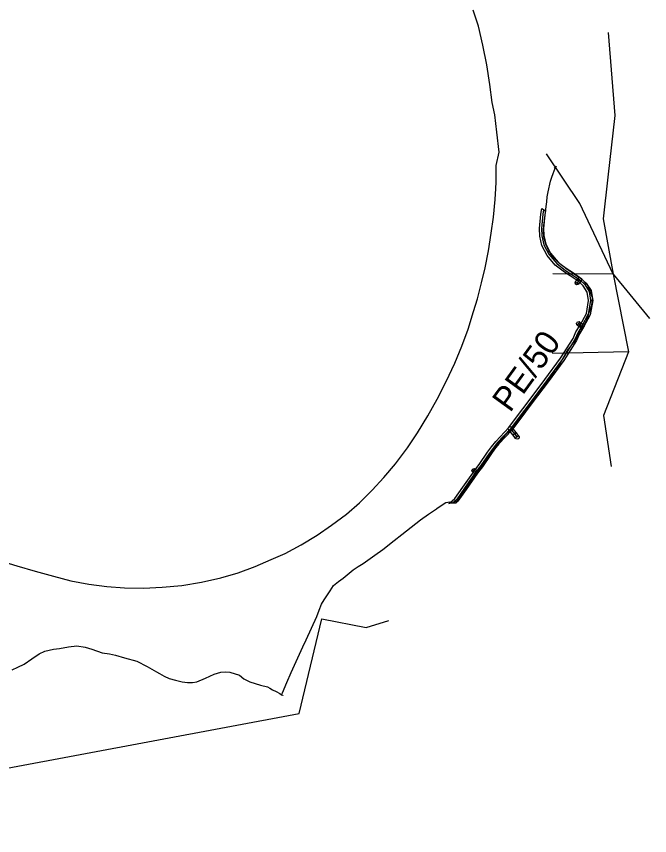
# Model space of a CAD drawing. Extents: x -555222 to -543220, y -1067119 to -1030889.
# Drawn here: x -549859.6 to -549545, y -1042854.2 to -1042447 of the extents above; entities that cross this region are included whole.
import ezdxf

# ---------------------------------------------------------------- set-up
doc = ezdxf.new("R2010")
doc.units = 0
for name, color, linetype in [('07_KANALIZACE', 7, 'Continuous'), ('07_OCH_P A POPISY TI', 7, 'Continuous'), ('07_PLYNOVOD', 7, 'Continuous'), ('07_SDĚLOVACÍ', 7, 'Continuous'), ('07_VODOVOD', 7, 'Continuous')]:
    doc.layers.add(name, color=color, linetype=linetype)

msp = doc.modelspace()

# ---------------------------------------------------------------- linework, layer by layer
at = {"layer": '07_KANALIZACE'}
msp.add_lwpolyline([(-550044.93, -1042883.73), (-550009.42, -1042847.76), (-549719.11, -1042793.56), (-549707.75, -1042746.36), (-549685.88, -1042750.73), (-549674.52, -1042747.24)], dxfattribs=at)
at = {"layer": '07_OCH_P A POPISY TI'}
for p, q in [((-549598.98, -1042545.22), (-549598.6, -1042542.52)), ((-549598.6, -1042542.52), (-549596.74, -1042543.68)), ((-549599.64, -1042552.35), (-549598.98, -1042545.22)), ((-549597, -1042545.46), (-549597.64, -1042552.39)), ((-549596.74, -1042543.68), (-549597, -1042545.46)), ((-549599.44, -1042556.17), (-549599.64, -1042552.35)), ((-549597.64, -1042552.39), (-549597.46, -1042555.91)), ((-549598.46, -1042560.84), (-549599.44, -1042556.17)), ((-549597.46, -1042555.91), (-549596.56, -1042560.16)), ((-549595.93, -1042565.77), (-549598.46, -1042560.84)), ((-549596.56, -1042560.16), (-549594.25, -1042564.65)), ((-549591.82, -1042570.6), (-549595.93, -1042565.77)), ((-549594.25, -1042564.65), (-549590.42, -1042569.14)), ((-549587.28, -1042574.12), (-549591.82, -1042570.6)), ((-549590.42, -1042569.14), (-549586.1, -1042572.5)), ((-549584.53, -1042576), (-549587.28, -1042574.12)), ((-549586.1, -1042572.5), (-549583.41, -1042574.34)), ((-549583.41, -1042574.34), (-549579.28, -1042577.05)), ((-549580.5, -1042578.65), (-549584.53, -1042576)), ((-549582.01, -1042579.22), (-549581.78, -1042578.87)), ((-549581.85, -1042580.03), (-549582.01, -1042579.22)), ((-549581.78, -1042578.87), (-549581.36, -1042578.24)), ((-549581.59, -1042578.58), (-549581.36, -1042578.24)), ((-549581.43, -1042579.4), (-549581.59, -1042578.58)), ((-549581.08, -1042579.63), (-549581.43, -1042579.4)), ((-549581.36, -1042578.24), (-549580.72, -1042577.29)), ((-549581.36, -1042578.24), (-549581.12, -1042577.9)), ((-549581.12, -1042577.9), (-549580.31, -1042577.74)), ((-549580.74, -1042579.86), (-549581.08, -1042579.63)), ((-549579.93, -1042579.7), (-549580.74, -1042579.86)), ((-549580.72, -1042577.29), (-549580.49, -1042576.95)), ((-549577.98, -1042580.89), (-549580.5, -1042578.65)), ((-549580.49, -1042576.95), (-549579.68, -1042576.79)), ((-549580.31, -1042577.74), (-549579.97, -1042577.97)), ((-549579.7, -1042579.36), (-549580.12, -1042579.99)), ((-549579.97, -1042577.97), (-549579.62, -1042578.2)), ((-549579.7, -1042579.36), (-549579.93, -1042579.7)), ((-549579.06, -1042578.41), (-549579.7, -1042579.36)), ((-549579.46, -1042579.01), (-549579.7, -1042579.36)), ((-549579.68, -1042576.79), (-549579.33, -1042577.02)), ((-549579.62, -1042578.2), (-549579.46, -1042579.01)), ((-549579.33, -1042577.02), (-549578.99, -1042577.25)), ((-549579.28, -1042577.05), (-549576.44, -1042579.57)), ((-549578.83, -1042578.06), (-549579.06, -1042578.41)), ((-549578.99, -1042577.25), (-549578.83, -1042578.06)), ((-549576.44, -1042579.57), (-549574.03, -1042583.31)), ((-549581.51, -1042580.26), (-549581.85, -1042580.03)), ((-549581.16, -1042580.49), (-549581.51, -1042580.26)), ((-549580.35, -1042580.33), (-549581.16, -1042580.49)), ((-549580.12, -1042579.99), (-549580.35, -1042580.33)), ((-549575.93, -1042584.05), (-549577.98, -1042580.89)), ((-549574.03, -1042583.31), (-549573.26, -1042588.15)), ((-549575.28, -1042588.13), (-549575.93, -1042584.05)), ((-549576.41, -1042594.73), (-549575.28, -1042588.13)), ((-549573.26, -1042588.15), (-549574.49, -1042595.39)), ((-549579.49, -1042600.44), (-549576.41, -1042594.73)), ((-549574.49, -1042595.39), (-549577.75, -1042601.44)), ((-549581.27, -1042599.53), (-549581.03, -1042599.19)), ((-549581.14, -1042600.35), (-549581.27, -1042599.53)), ((-549581.03, -1042599.19), (-549580.79, -1042598.86)), ((-549580.79, -1042598.86), (-549579.97, -1042598.73)), ((-549580.57, -1042600.04), (-549580.33, -1042599.7)), ((-549580.44, -1042600.86), (-549580.57, -1042600.04)), ((-549580.33, -1042599.7), (-549580.09, -1042599.37)), ((-549580.09, -1042599.37), (-549579.27, -1042599.24)), ((-549579.97, -1042598.73), (-549579.63, -1042598.97)), ((-549579.63, -1042598.97), (-549578.93, -1042599.48)), ((-549579.27, -1042599.24), (-549578.93, -1042599.48)), ((-549578.93, -1042599.48), (-549578.03, -1042600.13)), ((-549578.93, -1042599.48), (-549578.6, -1042599.72)), ((-549578.6, -1042599.72), (-549578.47, -1042600.54)), ((-549578.03, -1042600.13), (-549577.7, -1042600.37)), ((-549583.01, -1042607.1), (-549581.57, -1042603.8)), ((-549581.57, -1042603.8), (-549579.49, -1042600.44)), ((-549580.81, -1042600.59), (-549581.14, -1042600.35)), ((-549580.11, -1042601.1), (-549580.81, -1042600.59)), ((-549580.11, -1042601.1), (-549580.44, -1042600.86)), ((-549579.21, -1042601.75), (-549580.11, -1042601.1)), ((-549579.77, -1042601.34), (-549580.11, -1042601.1)), ((-549577.75, -1042601.44), (-549579.79, -1042604.74)), ((-549578.95, -1042601.21), (-549579.77, -1042601.34)), ((-549578.87, -1042601.99), (-549579.21, -1042601.75)), ((-549578.71, -1042600.88), (-549578.95, -1042601.21)), ((-549578.05, -1042601.86), (-549578.87, -1042601.99)), ((-549578.47, -1042600.54), (-549578.71, -1042600.88)), ((-549577.81, -1042601.53), (-549578.05, -1042601.86)), ((-549577.57, -1042601.19), (-549577.81, -1042601.53)), ((-549577.7, -1042600.37), (-549577.57, -1042601.19)), ((-549589.29, -1042616.92), (-549583.01, -1042607.1)), ((-549581.25, -1042608.04), (-549587.63, -1042618.04)), ((-549579.79, -1042604.74), (-549581.25, -1042608.04)), ((-549596.96, -1042627.5), (-549589.29, -1042616.92)), ((-549587.63, -1042618.04), (-549595.36, -1042628.7)), ((-549604.87, -1042637.91), (-549596.96, -1042627.5)), ((-549595.36, -1042628.7), (-549603.27, -1042639.11)), ((-549611.06, -1042646.19), (-549604.87, -1042637.91)), ((-549603.27, -1042639.11), (-549609.46, -1042647.39)), ((-549614.92, -1042651.28), (-549611.06, -1042646.19)), ((-549609.46, -1042647.39), (-549613.38, -1042652.58)), ((-549621.41, -1042658.23), (-549614.92, -1042651.28)), ((-549613.38, -1042652.58), (-549619.89, -1042659.53)), ((-549615.19, -1042652.24), (-549615.1, -1042651.41)), ((-549614.93, -1042652.56), (-549615.19, -1042652.24)), ((-549615.1, -1042651.41), (-549614.78, -1042651.15)), ((-549612.26, -1042655.87), (-549614.93, -1042652.56)), ((-549614.78, -1042651.15), (-549614.46, -1042650.89)), ((-549614.46, -1042650.89), (-549613.63, -1042650.98)), ((-549613.63, -1042650.98), (-549613.37, -1042651.3)), ((-549613.37, -1042651.3), (-549610.7, -1042654.61)), ((-549612.52, -1042655.55), (-549612.43, -1042654.72)), ((-549612.26, -1042655.87), (-549612.52, -1042655.55)), ((-549612.43, -1042654.72), (-549612.11, -1042654.46)), ((-549611.57, -1042656.73), (-549612.26, -1042655.87)), ((-549612, -1042656.19), (-549612.26, -1042655.87)), ((-549612.11, -1042654.46), (-549611.79, -1042654.2)), ((-549611.18, -1042656.28), (-549612, -1042656.19)), ((-549611.79, -1042654.2), (-549610.96, -1042654.29)), ((-549611.31, -1042657.05), (-549611.57, -1042656.73)), ((-549610.48, -1042657.14), (-549611.31, -1042657.05)), ((-549610.86, -1042656.02), (-549611.18, -1042656.28)), ((-549610.96, -1042654.29), (-549610.7, -1042654.61)), ((-549610.53, -1042655.76), (-549610.86, -1042656.02)), ((-549610.7, -1042654.61), (-549610.01, -1042655.47)), ((-549610.7, -1042654.61), (-549610.44, -1042654.94)), ((-549610.44, -1042654.94), (-549610.53, -1042655.76)), ((-549610.16, -1042656.88), (-549610.48, -1042657.14)), ((-549609.84, -1042656.62), (-549610.16, -1042656.88)), ((-549610.01, -1042655.47), (-549609.75, -1042655.8)), ((-549609.75, -1042655.8), (-549609.84, -1042656.62)), ((-549625.5, -1042663.6), (-549623.56, -1042660.96)), ((-549623.56, -1042660.96), (-549621.41, -1042658.23)), ((-549619.89, -1042659.53), (-549621.96, -1042662.16)), ((-549629.61, -1042669.66), (-549625.5, -1042663.6)), ((-549623.86, -1042664.76), (-549627.99, -1042670.84)), ((-549621.96, -1042662.16), (-549623.86, -1042664.76)), ((-549637.7, -1042680.93), (-549632.06, -1042672.83)), ((-549633.26, -1042672.47), (-549633.02, -1042672.13)), ((-549633.13, -1042673.28), (-549633.26, -1042672.47)), ((-549632.8, -1042673.53), (-549633.13, -1042673.28)), ((-549633.02, -1042672.13), (-549632.77, -1042671.8)), ((-549632.77, -1042671.8), (-549631.96, -1042671.67)), ((-549632.72, -1042672.86), (-549632.48, -1042672.52)), ((-549632.6, -1042673.68), (-549632.72, -1042672.86)), ((-549632.48, -1042672.52), (-549632.24, -1042672.19)), ((-549632.24, -1042672.19), (-549631.42, -1042672.06)), ((-549632.06, -1042672.83), (-549630.27, -1042670.51)), ((-549631.96, -1042671.67), (-549631.62, -1042671.91)), ((-549631.62, -1042671.91), (-549631.08, -1042672.3)), ((-549631.42, -1042672.06), (-549631.08, -1042672.3)), ((-549631.08, -1042672.3), (-549630.75, -1042672.55)), ((-549631.08, -1042672.3), (-549630.66, -1042672.61)), ((-549630.62, -1042673.37), (-549630.86, -1042673.7)), ((-549630.75, -1042672.55), (-549630.62, -1042673.37)), ((-549630.66, -1042672.61), (-549630.33, -1042672.86)), ((-549628.68, -1042671.74), (-549630.44, -1042674.01)), ((-549630.33, -1042672.86), (-549630.2, -1042673.68)), ((-549630.27, -1042670.51), (-549629.61, -1042669.66)), ((-549627.99, -1042670.84), (-549628.68, -1042671.74)), ((-549630.44, -1042674.01), (-549636.06, -1042682.07)), ((-549632.26, -1042673.92), (-549632.8, -1042673.53)), ((-549632.26, -1042673.92), (-549632.6, -1042673.68)), ((-549631.93, -1042674.16), (-549632.26, -1042673.92)), ((-549631.84, -1042674.23), (-549632.26, -1042673.92)), ((-549631.11, -1042674.04), (-549631.93, -1042674.16)), ((-549631.5, -1042674.47), (-549631.84, -1042674.23)), ((-549630.69, -1042674.34), (-549631.5, -1042674.47)), ((-549630.86, -1042673.7), (-549631.11, -1042674.04)), ((-549630.44, -1042674.01), (-549630.69, -1042674.34)), ((-549630.2, -1042673.68), (-549630.44, -1042674.01)), ((-549641.74, -1042686.65), (-549637.7, -1042680.93)), ((-549636.06, -1042682.07), (-549640.24, -1042687.99)), ((-549641.24, -1042688.87), (-549644.7, -1042689.18)), ((-549644.7, -1042689.18), (-549644.41, -1042688.98)), ((-549644.41, -1042688.98), (-549641.74, -1042686.65)), ((-549640.24, -1042687.99), (-549641.24, -1042688.87))]:
    msp.add_line(p, q, dxfattribs=at)
at = {"layer": '07_PLYNOVOD'}
for points in [[(-549597.67, -1042543.1), (-549597.99, -1042545.34), (-549598.64, -1042552.37), (-549598.45, -1042556.04), (-549597.51, -1042560.5), (-549595.09, -1042565.21), (-549591.12, -1042569.87), (-549586.69, -1042573.31), (-549583.97, -1042575.17), (-549579.89, -1042577.85), (-549577.21, -1042580.23), (-549574.98, -1042583.68), (-549574.27, -1042588.14), (-549575.45, -1042595.06), (-549578.62, -1042600.94), (-549580.68, -1042604.27), (-549582.13, -1042607.57), (-549588.46, -1042617.48), (-549596.16, -1042628.1), (-549604.07, -1042638.51), (-549610.26, -1042646.79), (-549614.15, -1042651.93), (-549620.65, -1042658.88), (-549622.76, -1042661.56), (-549624.68, -1042664.18), (-549628.8, -1042670.25), (-549629.48, -1042671.12), (-549631.25, -1042673.42), (-549636.88, -1042681.5), (-549640.99, -1042687.32), (-549642.93, -1042689.02)], [(-549580.53, -1042578.8), (-549580.95, -1042579.43)], [(-549579.89, -1042577.85), (-549580.53, -1042578.8)], [(-549580.22, -1042599.78), (-549579.52, -1042600.29)], [(-549579.52, -1042600.29), (-549578.62, -1042600.94)], [(-549614.15, -1042651.93), (-549611.48, -1042655.24)], [(-549611.48, -1042655.24), (-549610.79, -1042656.1)], [(-549631.67, -1042673.11), (-549632.21, -1042672.72)], [(-549631.25, -1042673.42), (-549631.67, -1042673.11)]]:
    msp.add_lwpolyline(points, dxfattribs=at)
at = {"layer": '07_SDĚLOVACÍ'}
for points in [[(-549868.78, -1042717.33), (-549859.39, -1042720.17), (-549850.22, -1042722.8), (-549841.15, -1042725.3), (-549832.55, -1042727.49), (-549823.57, -1042729.19), (-549814.7, -1042730.35), (-549805.87, -1042731.01), (-549796.46, -1042731.2), (-549787.11, -1042730.77), (-549777.35, -1042729.84), (-549767.65, -1042728.18), (-549757.98, -1042726.07), (-549749.44, -1042723.58), (-549741, -1042720.42), (-549732.96, -1042717.01), (-549726.04, -1042713.99), (-549718.12, -1042709.71), (-549710.2, -1042704.92), (-549703, -1042699.94), (-549695.62, -1042694.35), (-549689.13, -1042688.75), (-549682.79, -1042682.42), (-549677.08, -1042676.26), (-549671.27, -1042669.4), (-549665.21, -1042661.46), (-549660.25, -1042653.97), (-549655.23, -1042645.54), (-549650.52, -1042637.32), (-549646.06, -1042628.42), (-549641.79, -1042619.38), (-549638.32, -1042610.97), (-549635.19, -1042602.41), (-549632.41, -1042593.62), (-549630.53, -1042587.39), (-549628.48, -1042579.45), (-549626.7, -1042572.04), (-549625.05, -1042563.46), (-549623.76, -1042554.82), (-549622.61, -1042546.72), (-549621.76, -1042538.06), (-549621.34, -1042532.56), (-549621.23, -1042529.38), (-549621.27, -1042521.15), (-549619.7, -1042514.51), (-549620.91, -1042504.6), (-549621.91, -1042495.95), (-549623.17, -1042489.75), (-549624.32, -1042480.77), (-549625.85, -1042471.04), (-549627.76, -1042461.25), (-549630.04, -1042451.84), (-549632.63, -1042443.84)], [(-549565.57, -1042455.05), (-549562.28, -1042496.24), (-549565.78, -1042526.94), (-549568.13, -1042547.58), (-549563.06, -1042575.05)], [(-549563.06, -1042575.05), (-549579.64, -1042540.02), (-549596.14, -1042515.3)], [(-549563.06, -1042575.05), (-549555.5, -1042613.68), (-549593.09, -1042614.56), (-549593.4, -1042613.96)], [(-549563.06, -1042575.05), (-549593.05, -1042574.97)], [(-549563.06, -1042575.05), (-549544.98, -1042597.24)], [(-549555.5, -1042613.68), (-549567.96, -1042645.37), (-549564.08, -1042670.68)]]:
    msp.add_lwpolyline(points, dxfattribs=at)
at = {"layer": '07_VODOVOD'}
for p, q in [((-549592.26, -1042522.26), (-549592.48, -1042522.16)), ((-549591.86, -1042522.49), (-549592.26, -1042522.26)), ((-549591.27, -1042521.52), (-549591.27, -1042521.52)), ((-549591.27, -1042521.52), (-549591.27, -1042521.52)), ((-549596.38, -1042541.56), (-549596.5, -1042541.51)), ((-549577.39, -1042579.01), (-549577.43, -1042579.08)), ((-549618.59, -1042657.2), (-549618.55, -1042657.32)), ((-549650.73, -1042691.61), (-549650.86, -1042691.49)), ((-549848.2, -1042763.79), (-549848.19, -1042763.96)), ((-549789.92, -1042772.8), (-549789.99, -1042772.9)), ((-549728.77, -1042783.5), (-549728.82, -1042783.64)), ((-549727.81, -1042784.13), (-549727.21, -1042784.38)), ((-549727.21, -1042784.38), (-549727.15, -1042784.46))]:
    msp.add_line(p, q, dxfattribs=at)
msp.add_lwpolyline([(-549861.62, -1042771.85), (-549858.88, -1042770.42), (-549855.69, -1042768.89), (-549851.94, -1042766.34), (-549848.2, -1042763.79), (-549845.44, -1042762.53), (-549841.07, -1042761.48), (-549838.21, -1042761.19), (-549833.75, -1042760.32), (-549829.48, -1042759.78), (-549825.38, -1042760.46), (-549822.08, -1042761.44), (-549816.92, -1042763.27), (-549813.24, -1042763.88), (-549810.42, -1042764.44), (-549805.82, -1042765.76), (-549799.8, -1042767.47), (-549794.53, -1042770.19), (-549789.92, -1042772.8), (-549788.43, -1042773.63), (-549786.08, -1042774.89), (-549783.73, -1042776.15), (-549780.48, -1042776.92), (-549777.24, -1042777.69), (-549774.51, -1042778.15), (-549772.02, -1042778.16), (-549769.91, -1042777.73), (-549765.63, -1042775.92), (-549761.3, -1042773.97), (-549757.97, -1042772.92), (-549755.46, -1042772.72), (-549753.51, -1042772.99), (-549748.79, -1042774.44), (-549746.54, -1042776.22), (-549743.54, -1042777.73), (-549740.91, -1042778.57), (-549738.28, -1042779.41), (-549734.88, -1042780.18), (-549733.63, -1042780.92), (-549732.38, -1042781.66), (-549730.58, -1042782.58), (-549728.77, -1042783.5), (-549727.81, -1042784.13), (-549727.45, -1042783.16), (-549725.24, -1042778.12), (-549723.04, -1042773.07), (-549718.97, -1042763.97), (-549717.31, -1042760.43), (-549715.65, -1042756.89), (-549713, -1042751.08), (-549710.35, -1042745.27), (-549709.16, -1042742.17), (-549707.98, -1042739.07), (-549706.64, -1042737.02), (-549705.31, -1042734.98), (-549703.68, -1042732.44), (-549702.06, -1042729.9), (-549699.57, -1042727.83), (-549697.19, -1042726.26), (-549692.25, -1042722.12), (-549689.8, -1042720.5), (-549687.35, -1042718.89), (-549681.49, -1042714.85), (-549677.45, -1042711.95), (-549671.82, -1042707.54), (-549668.14, -1042704.45), (-549658.74, -1042697.21), (-549654.84, -1042694.47), (-549650.94, -1042691.73), (-549650.73, -1042691.61), (-549648.46, -1042690.08), (-549646.18, -1042688.54), (-549644.28, -1042688.31), (-549642.94, -1042688.7), (-549640.25, -1042687.78), (-549639.42, -1042686.45), (-549638.6, -1042685.12), (-549635.2, -1042680.22), (-549631.81, -1042675.31), (-549630.16, -1042673.04), (-549629.44, -1042672), (-549627.28, -1042668.86), (-549624.84, -1042665.63), (-549621.72, -1042661.42), (-549618.59, -1042657.2), (-549615.53, -1042653.99), (-549613.46, -1042651.81), (-549609.73, -1042647.14), (-549604.86, -1042641.02), (-549602.63, -1042637.8), (-549595.37, -1042628.15), (-549591.64, -1042623.26), (-549588.7, -1042618.33), (-549585.86, -1042613.3), (-549582.12, -1042608.38), (-549579.39, -1042603.76), (-549577.72, -1042600.75), (-549576.25, -1042597.97), (-549575.08, -1042594.12), (-549573.74, -1042590.7), (-549573.52, -1042588.7), (-549573.31, -1042586.71), (-549574.46, -1042583.66), (-549575.61, -1042580.79), (-549576.5, -1042579.9), (-549577.39, -1042579.01), (-549578.7, -1042577.68), (-549579.85, -1042576.83), (-549582.82, -1042574.66), (-549586.49, -1042572.25), (-549589.61, -1042570), (-549591.12, -1042568.53), (-549592.64, -1042567.06), (-549594.99, -1042563.47), (-549596.54, -1042560.15), (-549597.59, -1042556.58), (-549597.65, -1042553.36), (-549597.46, -1042550.97), (-549597.27, -1042548.58), (-549596.92, -1042545.8), (-549596.57, -1042543.02), (-549596.38, -1042541.56), (-549596.09, -1042539.13), (-549595.8, -1042536.7), (-549595.32, -1042534.15), (-549594.2, -1042528.86), (-549593.55, -1042526.99), (-549592.9, -1042525.12), (-549592.38, -1042523.8), (-549591.86, -1042522.49), (-549591.56, -1042522), (-549591.27, -1042521.52)], dxfattribs=at)

# ---------------------------------------------------------------- texts
at = {"layer": '07_OCH_P A POPISY TI'}
msp.add_text('PE/50', height=12, rotation=54.0561, dxfattribs=at).set_placement((-549614.31, -1042644.33))

doc.saveas('drawing.dxf')
